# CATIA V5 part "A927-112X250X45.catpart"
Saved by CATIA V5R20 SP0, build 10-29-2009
Part number: A927-112X250X45
Source: Unknown
Property "A": "50.000"
Property "ARTICLENO": "A927-112X250X45"
Property "BOMINFO": "A927-112X250X45"
Property "CODE": "A927-112X250X45"
Property "CREATOR": "CADENAS GmbH"
Property "D": "18.000"
Property "D1": "26.000"
Property "F": "28.000"
Property "FORM": "A"
Property "L": "250.000"
Property "L1": "100.000"
Property "L2": "20.000"
Property "L3": "50.000"
Property "LINA": "A927-112X250X45"
Property "NB": "A927-112X250X45"
Property "NBSYN": "$CODE."
Property "NN": "A927"
Property "NT": "VDI 3387 Removable Die Heels, steel and self-lubricating"
Property "R": "25.000"
Property "S": "45.000"
Property "SUPPLIER": "CF"
Property "T": "21.000"
Property "W": "112.000"
Bounding box of the stored display mesh (mm): x -56 to 56, y 0 to 250, z -45 to 0
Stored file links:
  C:\Users\borellobunino\Desktop\3D X SITO CF\A927\GSB_OILLESS_G2290511225045\CATIAV5\A927-112X250X45.catpart
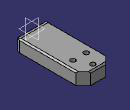
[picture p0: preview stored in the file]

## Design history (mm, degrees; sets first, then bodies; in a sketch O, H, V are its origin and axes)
Body1 "Geometry.1" (main body)
  Solid1 "A927-112X250X45.catpart": solid without history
